AutomationDirect Productivity Suite project: EIP_GS30 (software 4.2.0 (39))
author: Test
Rung notation: left to right = series (deeper-indented lines continue the line above), [a | b] = parallel branches, -- = plain wire, BOX.Pin = further input of the box above; 'quoted' = tag name, ? = field left empty; instruction and field names as stored in the project; options that are off are not listed.

HARDWARE
  EtherNet/IP device: E/IP Scanner "GS30"
    with: GS30A-CM-EIP1 "GS30A-CM-EIP1"
  Base 1 (1 slots)
    slot 0: P1-550

STRUCTURES
STRUCTURE GS30_Status
  Fault_Code : Uint8, strLength=15
  Warning_Code : Uint8, strLength=15
  Stop : Boolean, strLength=15
  Decel_During_Stop : Boolean, strLength=15
  Standby : Boolean, strLength=15
  Run : Boolean, strLength=15
  JOG_Active : Boolean, strLength=15
  Forward : Boolean, strLength=15
  Transition_Rev_To_FWD : Boolean, strLength=15
  Transition_FWD_To_REV : Boolean, strLength=15
  Reverse : Boolean, strLength=15
  Main_Freq_From_Comm_Interface : Boolean, strLength=15
  Main_Freq_From_Analog : Boolean, strLength=15
  CMD_Operated_By_Comm_Interface : Boolean, strLength=15
  Params_Have_Been_Locked : Boolean, strLength=15
  Drive_Stopped : Boolean, strLength=15
  Drive_Running : Boolean, strLength=15
  Frequency_Command : Int16, strLength=15
  Output_Frequency : Int16, strLength=15
  Output_Current : Int16, strLength=15
  DC_Bus_Voltage : Int16, strLength=15
  Output_Voltage : Int16, strLength=15
  MultiSpeed_Or_PID_Input_StepNo : Int16, strLength=15
  Max_Output_Torque_N-m : Int16, strLength=15
  Digital_Input_Counter_Value : Int16, strLength=15
  Power_Factor_Angle : Int16, strLength=15
  Output_Torque : Int16, strLength=15
  Actual_Motor_Speed_RPM : Int16, strLength=15
  PG1_Feedback_Count : Int16, strLength=15
  PG2_Pulse_Count : Int16, strLength=15
  Power_Output_kW : Int16, strLength=15
STRUCTURE GS30_Command
  Stop : Boolean, strLength=15
  Run_Forward : Boolean, strLength=15
  Run_Reverse : Boolean, strLength=15
  JOG_Forward : Boolean, strLength=15
  JOG_Reverse : Boolean, strLength=15
  Frequency_Command : Uint16, strLength=15
  JOG_Frequency : Array of Uint16, dimensions=1, strLength=15

TAGS  (name : type @system ID = initial value)
  GS30_EIP_INPUTS : Array[16] of Uint16 @AR1US16-000004
  GS30_EIP_OUTPUTS : Array[3] of Int16 @AR1S16-000002
  GS30_ExtendedStatus : Array[8] of Uint16 @AR1US16-000001
  GS30_Status : GS30_Status @USTRUC-000001
  ExpDataInput : Array[6] of Uint8 @AR1US8-000001
  ExpDataInput2 : Array[1] of Uint16 @AR1US16-000003
  'Exp Set' : Boolean @C-000062
  'Exp Get' : Boolean @C-000073
  'Enable_E/IP' : Boolean @C-000079
  TwoBytes : Array[2] of Uint8 @AR1US8-000002
  GS30_IP_Address : String(15) @STR-000024
  GS30_Command : GS30_Command @USTRUC-000003
  Blank_IP : Boolean @C-000085
  GS30_IP_Address_Length : Uint16 @US16-000004

SYSTEM TAGS USED OR MAPPED TO MODBUS
  GS30_ExpRead1 : EMSG @SSTRUC-000004  // System Structure for EtherNet/IP Explicit Message
  GS30_ExpRead2 : EMSG @SSTRUC-000005  // System Structure for EtherNet/IP Explicit Message

TASK Main  (Run Every Scan)
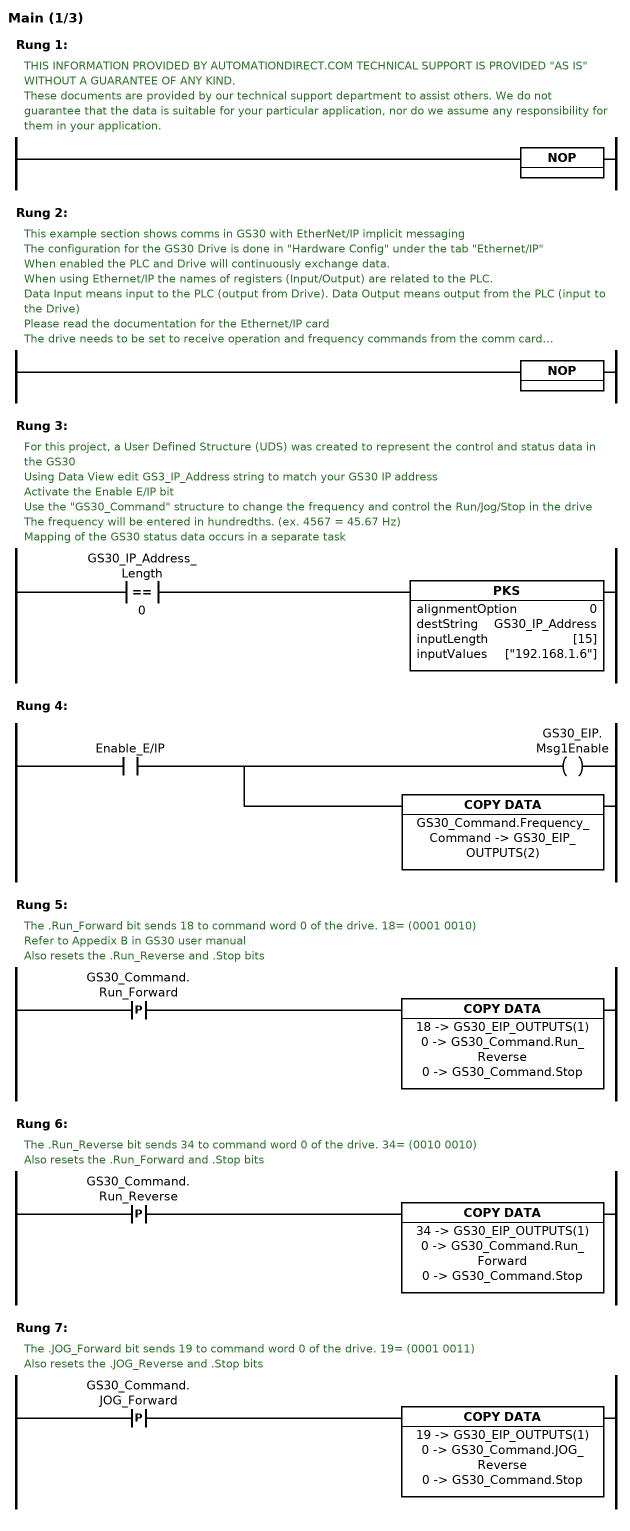
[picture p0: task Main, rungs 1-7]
Rung 1:
  // THIS INFORMATION PROVIDED BY AUTOMATIONDIRECT.COM TECHNICAL SUPPORT IS PROVIDED "AS IS" WITHOUT A GUARANTEE OF ANY KIND.
  // These documents are provided by our technical support department to assist others. We do not guarantee that the data is suitable for your particular application, nor do we assume any responsibility for them in your application.
  NOP()
Rung 2:
  // This example section shows comms in GS30 with EtherNet/IP implicit messaging
  // The configuration for the GS30 Drive is done in "Hardware Config" under the tab "Ethernet/IP"
  // When enabled the PLC and Drive will continuously exchange data.
  // When using Ethernet/IP the names of registers (Input/Output) are related to the PLC.
  // Data Input means input to the PLC (output from Drive). Data Output means output from the PLC (input to the Drive)
  // Please read the documentation for the Ethernet/IP card
  // The drive needs to be set to receive operation and frequency commands from the comm card.
  // GS30: P00.20=8/P00.21=5 (Remote) or P00.30=8/P00.31=5 (Local)
  // P09.74= 0 (Both) or 1 (EtherNet/IP)
  NOP()
Rung 3:
  // For this project, a User Defined Structure (UDS) was created to represent the control and status data in the GS30
  // Using Data View edit GS3_IP_Address string to match your GS30 IP address
  // Activate the Enable E/IP bit
  // Use the "GS30_Command" structure to change the frequency and control the Run/Jog/Stop in the drive
  // The frequency will be entered in hundredths. (ex. 4567 = 45.67 Hz)
  // Mapping of the GS30 status data occurs in a separate task
  COMP(GS30_IP_Address_Length = 0)
    PKS(alignmentOption=0, destString=GS30_IP_Address, inputLength=[15], inputValues=["192.168.1.6"])
Rung 4:
  NO('Enable_E/IP') [OUT(GS30_EIP.Msg1Enable) | CPY(GS30_Command.Frequency_Command -> GS30_EIP_OUTPUTS(2))]
Rung 5:
  // The .Run_Forward bit sends 18 to command word 0 of the drive. 18= (0001 0010)
  // Refer to Appedix B in GS30 user manual
  // Also resets the .Run_Reverse and .Stop bits
  NOE(GS30_Command.Run_Forward, rising)
    CPY(18 -> GS30_EIP_OUTPUTS(1), 0 -> GS30_Command.Run_Reverse, 0 -> GS30_Command.Stop)
Rung 6:
  // The .Run_Reverse bit sends 34 to command word 0 of the drive. 34= (0010 0010)
  // Also resets the .Run_Forward and .Stop bits
  NOE(GS30_Command.Run_Reverse, rising)
    CPY(34 -> GS30_EIP_OUTPUTS(1), 0 -> GS30_Command.Run_Forward, 0 -> GS30_Command.Stop)
Rung 7:
  // The .JOG_Forward bit sends 19 to command word 0 of the drive. 19= (0001 0011)
  // Also resets the .JOG_Reverse and .Stop bits
  NOE(GS30_Command.JOG_Forward, rising)
    CPY(19 -> GS30_EIP_OUTPUTS(1), 0 -> GS30_Command.JOG_Reverse, 0 -> GS30_Command.Stop)
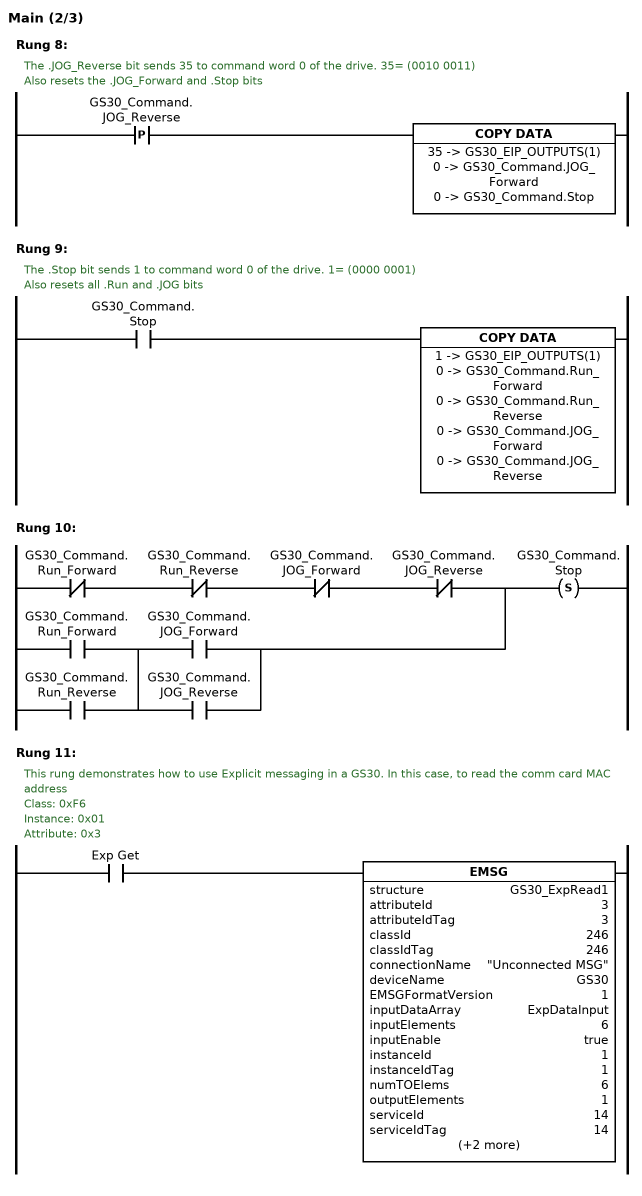
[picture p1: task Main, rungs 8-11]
Rung 8:
  // The .JOG_Reverse bit sends 35 to command word 0 of the drive. 35= (0010 0011)
  // Also resets the .JOG_Forward and .Stop bits
  NOE(GS30_Command.JOG_Reverse, rising)
    CPY(35 -> GS30_EIP_OUTPUTS(1), 0 -> GS30_Command.JOG_Forward, 0 -> GS30_Command.Stop)
Rung 9:
  // The .Stop bit sends 1 to command word 0 of the drive. 1= (0000 0001)
  // Also resets all .Run and .JOG bits
  NO(GS30_Command.Stop)
    CPY(1 -> GS30_EIP_OUTPUTS(1), 0 -> GS30_Command.Run_Forward, 0 -> GS30_Command.Run_Reverse, 0 -> GS30_Command.JOG_Forward, 0 -> GS30_Command.JOG_Reverse)
Rung 10:
  [ NC(GS30_Command.Run_Forward) NC(GS30_Command.Run_Reverse) NC(GS30_Command.JOG_Forward)
      NC(GS30_Command.JOG_Reverse)
    | [NO(GS30_Command.Run_Forward) | NO(GS30_Command.Run_Reverse)]
      [NO(GS30_Command.JOG_Forward) | NO(GS30_Command.JOG_Reverse)] ]
    SET(GS30_Command.Stop)
Rung 11:
  // This rung demonstrates how to use Explicit messaging in a GS30. In this case, to read the comm card MAC address
  // Class: 0xF6
  // Instance: 0x01
  // Attribute: 0x3
  NO('Exp Get')
    EMSG(structure=GS30_ExpRead1, attributeId=3, attributeIdTag=3, classId=246, classIdTag=246, connectionName="Unconnected MSG", deviceName=GS30, EMSGFormatVersion=1, inputDataArray=ExpDataInput, inputElements=6, inputEnable, instanceId=1, instanceIdTag=1, numTOElems=6, outputElements=1, serviceId=14, serviceIdTag=14, serviceName=Generic, useAttributeId)
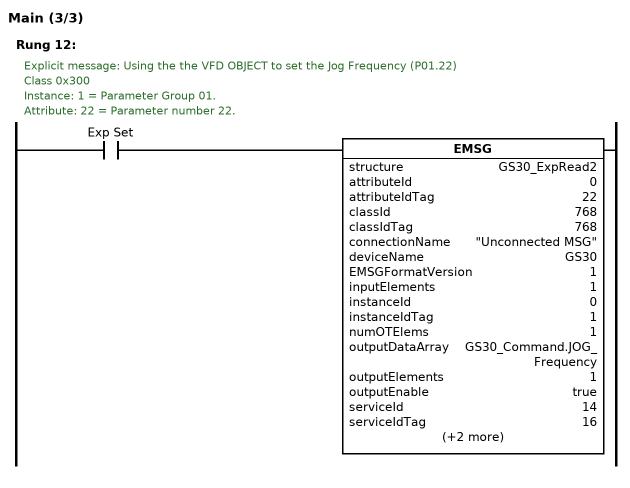
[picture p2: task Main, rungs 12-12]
Rung 12:
  // Explicit message: Using the the VFD OBJECT to set the Jog Frequency (P01.22)
  // Class 0x300
  // Instance: 1 = Parameter Group 01.
  // Attribute: 22 = Parameter number 22.
  NO('Exp Set')
    EMSG(structure=GS30_ExpRead2, attributeId=0, attributeIdTag=22, classId=768, classIdTag=768, connectionName="Unconnected MSG", deviceName=GS30, EMSGFormatVersion=1, inputElements=1, instanceId=0, instanceIdTag=1, numOTElems=1, outputDataArray=GS30_Command.JOG_Frequency, outputElements=1, outputEnable, serviceId=14, serviceIdTag=16, serviceName=Generic, useAttributeId)

TASK GS30_Status_Mapping  (Run Every Scan)
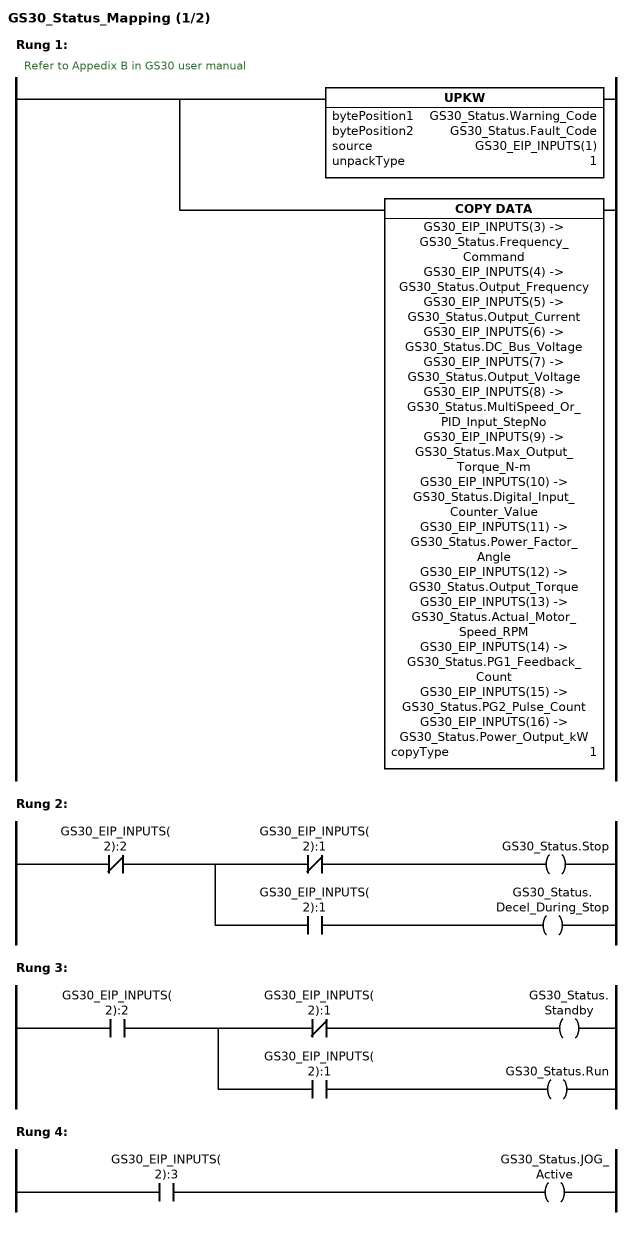
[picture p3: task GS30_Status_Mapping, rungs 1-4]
Rung 1:
  // Refer to Appedix B in GS30 user manual
  UPKW(bytePosition1=GS30_Status.Warning_Code, bytePosition2=GS30_Status.Fault_Code, source=GS30_EIP_INPUTS(1), unpackType=1)
  CPY(GS30_EIP_INPUTS(3) -> GS30_Status.Frequency_Command, GS30_EIP_INPUTS(4) -> GS30_Status.Output_Frequency, GS30_EIP_INPUTS(5) -> GS30_Status.Output_Current, GS30_EIP_INPUTS(6) -> GS30_Status.DC_Bus_Voltage, GS30_EIP_INPUTS(7) -> GS30_Status.Output_Voltage, GS30_EIP_INPUTS(8) -> GS30_Status.MultiSpeed_Or_PID_Input_StepNo, GS30_EIP_INPUTS(9) -> GS30_Status.Max_Output_Torque_N-m, GS30_EIP_INPUTS(10) -> GS30_Status.Digital_Input_Counter_Value, GS30_EIP_INPUTS(11) -> GS30_Status.Power_Factor_Angle, GS30_EIP_INPUTS(12) -> GS30_Status.Output_Torque, GS30_EIP_INPUTS(13) -> GS30_Status.Actual_Motor_Speed_RPM, GS30_EIP_INPUTS(14) -> GS30_Status.PG1_Feedback_Count, GS30_EIP_INPUTS(15) -> GS30_Status.PG2_Pulse_Count, GS30_EIP_INPUTS(16) -> GS30_Status.Power_Output_kW, copyType=1)
Rung 2:
  NC(GS30_EIP_INPUTS(2):2)
    [NC(GS30_EIP_INPUTS(2):1) OUT(GS30_Status.Stop) | NO(GS30_EIP_INPUTS(2):1) OUT(GS30_Status.Decel_During_Stop)]
Rung 3:
  NO(GS30_EIP_INPUTS(2):2)
    [NC(GS30_EIP_INPUTS(2):1) OUT(GS30_Status.Standby) | NO(GS30_EIP_INPUTS(2):1) OUT(GS30_Status.Run)]
Rung 4:
  NO(GS30_EIP_INPUTS(2):3) OUT(GS30_Status.JOG_Active)
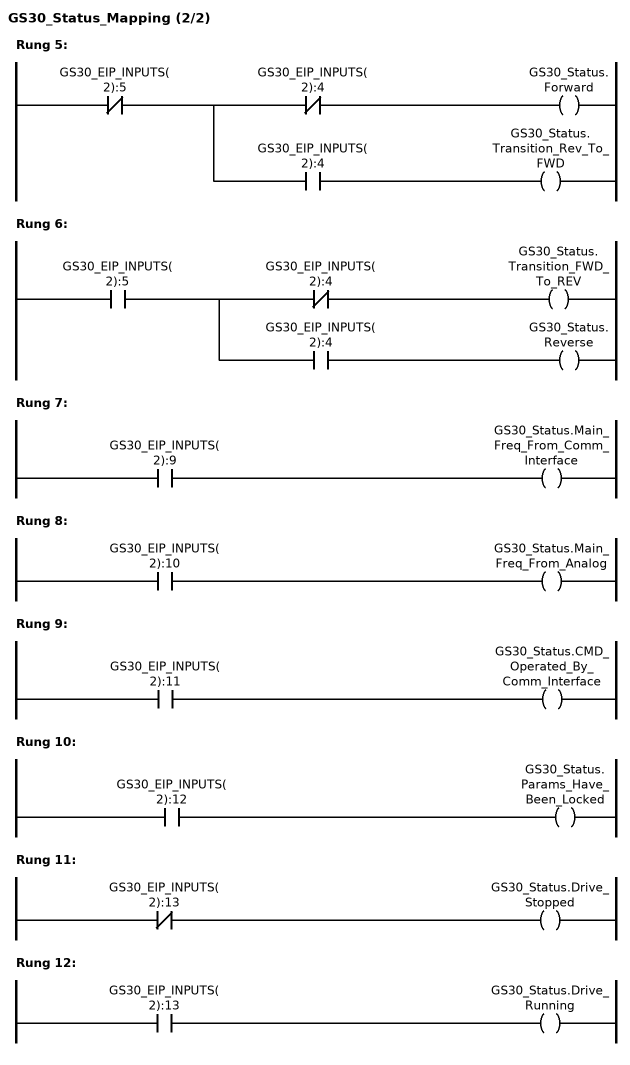
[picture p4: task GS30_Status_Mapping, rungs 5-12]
Rung 5:
  NC(GS30_EIP_INPUTS(2):5)
    [ NC(GS30_EIP_INPUTS(2):4) OUT(GS30_Status.Forward)
    | NO(GS30_EIP_INPUTS(2):4) OUT(GS30_Status.Transition_Rev_To_FWD) ]
Rung 6:
  NO(GS30_EIP_INPUTS(2):5)
    [ NC(GS30_EIP_INPUTS(2):4) OUT(GS30_Status.Transition_FWD_To_REV)
    | NO(GS30_EIP_INPUTS(2):4) OUT(GS30_Status.Reverse) ]
Rung 7:
  NO(GS30_EIP_INPUTS(2):9) OUT(GS30_Status.Main_Freq_From_Comm_Interface)
Rung 8:
  NO(GS30_EIP_INPUTS(2):10) OUT(GS30_Status.Main_Freq_From_Analog)
Rung 9:
  NO(GS30_EIP_INPUTS(2):11) OUT(GS30_Status.CMD_Operated_By_Comm_Interface)
Rung 10:
  NO(GS30_EIP_INPUTS(2):12) OUT(GS30_Status.Params_Have_Been_Locked)
Rung 11:
  NC(GS30_EIP_INPUTS(2):13) OUT(GS30_Status.Drive_Stopped)
Rung 12:
  NO(GS30_EIP_INPUTS(2):13) OUT(GS30_Status.Drive_Running)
